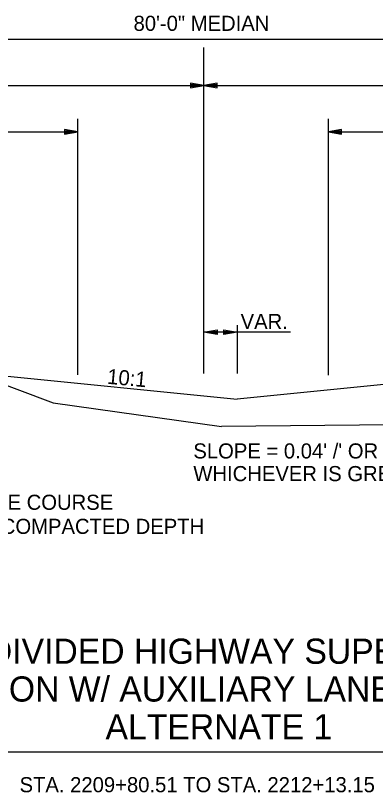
# Model space of a CAD drawing. Extents: x 1734743 to 1735935, y 759845 to 763831.
# Drawn here: x 1735746 to 1735774.6, y 762828.8 to 762890.5 of the extents above; entities that cross this region are included whole.
import ezdxf

# ---------------------------------------------------------------- set-up
doc = ezdxf.new("R2010")
doc.units = 0
for name, color, linetype in [('1', 7, 'Continuous'), ('10', 7, 'Continuous'), ('11', 7, 'Continuous'), ('19', 7, 'Continuous'), ('7', 7, 'Continuous'), ('9', 7, 'Continuous')]:
    doc.layers.add(name, color=color, linetype=linetype)

msp = doc.modelspace()

# ---------------------------------------------------------------- linework, layer by layer
at = {"layer": '1'}
msp.add_line((1735726.589, 762832.047), (1735798.51, 762832.047), dxfattribs=at)
at = {"layer": '11'}
msp.add_line((1735792.763, 762858.202), (1735762.354, 762857.892), dxfattribs=at)
at = {"layer": '19'}
for p, q in [((1735720.967, 762888.656), (1735800.967, 762888.656)), ((1735759.917, 762885.153), (1735759.917, 762884.786)), ((1735760.967, 762884.97), (1735759.917, 762885.153)), ((1735760.687, 762884.996), (1735759.917, 762885.057)), ((1735762.017, 762885.153), (1735760.967, 762884.97)), ((1735762.017, 762885.057), (1735761.247, 762884.996)), ((1735762.017, 762884.786), (1735762.017, 762885.153)), ((1735720.967, 762884.97), (1735760.967, 762884.97)), ((1735759.917, 762884.786), (1735760.967, 762884.97)), ((1735759.917, 762884.873), (1735760.687, 762884.943)), ((1735760.967, 762884.97), (1735762.017, 762884.786)), ((1735760.967, 762884.97), (1735800.967, 762884.97)), ((1735761.247, 762884.943), (1735762.017, 762884.873)), ((1735750.967, 762864.527), (1735750.967, 762882.329)), ((1735770.842, 762864.527), (1735770.842, 762882.329)), ((1735749.917, 762881.467), (1735749.917, 762881.099)), ((1735750.967, 762881.283), (1735749.917, 762881.467)), ((1735750.687, 762881.309), (1735749.917, 762881.37)), ((1735771.892, 762881.467), (1735770.842, 762881.283)), ((1735771.892, 762881.37), (1735771.122, 762881.309)), ((1735771.892, 762881.099), (1735771.892, 762881.467)), ((1735720.967, 762881.283), (1735750.967, 762881.283)), ((1735749.917, 762881.099), (1735750.967, 762881.283)), ((1735749.917, 762881.187), (1735750.687, 762881.257)), ((1735770.842, 762881.283), (1735771.892, 762881.099)), ((1735770.842, 762881.283), (1735800.967, 762881.283)), ((1735771.122, 762881.257), (1735771.892, 762881.187)), ((1735760.969, 762865.372), (1735762.019, 762865.556)), ((1735762.019, 762865.188), (1735760.969, 762865.372)), ((1735761.249, 762865.398), (1735762.019, 762865.459)), ((1735762.019, 762865.276), (1735761.249, 762865.346)), ((1735762.019, 762865.556), (1735762.019, 762865.188)), ((1735762.555, 762865.188), (1735762.555, 762865.556)), ((1735762.555, 762865.556), (1735763.605, 762865.372)), ((1735762.555, 762865.468), (1735763.325, 762865.398)), ((1735763.605, 762865.372), (1735762.555, 762865.188)), ((1735763.325, 762865.346), (1735762.555, 762865.284)), ((1735750.967, 762862.001), (1735750.967, 762864.527)), ((1735770.842, 762861.972), (1735770.842, 762864.527)), ((1735741.096, 762862.307), (1735763.605, 762860.056)), ((1735782.461, 762861.942), (1735763.605, 762860.056))]:
    msp.add_line(p, q, dxfattribs=at)
msp.add_lwpolyline([(1735716.449, 762866.88), (1735723.531, 762867.254), (1735735.42, 762864.874), (1735749.006, 762859.774), (1735762.354, 762857.892)], dxfattribs=at)
at = {"layer": '7'}
msp.add_line((1735760.969, 762862.101), (1735760.969, 762887.988), dxfattribs=at)
at = {"layer": '9'}
for p, q in [((1735763.605, 762865.926), (1735763.605, 762862.101)), ((1735767.85, 762865.372), (1735760.969, 762865.372))]:
    msp.add_line(p, q, dxfattribs=at)

# ---------------------------------------------------------------- texts
at = {"layer": '10'}
for s, height, p in [('VAR.', 1.2, (1735763.883, 762865.631)), ("SLOPE = 0.04' /' OR S.E. SLOPE", 1.2, (1735760.133, 762855.349)), ('WHICHEVER IS GREATER', 1.2, (1735760.133, 762853.549)), ('I-57 TYPICAL DIVIDED HIGHWAY SUPERELEVATED', 2, (1735726.589, 762839.047)), ('SECTION W/ AUXILIARY LANE LT.', 2, (1735737.62, 762836.047)), ('ALTERNATE 1', 2, (1735753.164, 762833.047))]:
    msp.add_text(s, height=height, dxfattribs=at).set_placement(p)
at = {"layer": '19'}
for s, p in [('80\'-0" MEDIAN', (1735755.389, 762889.303)), ('STA. 2209+80.51 TO STA. 2212+13.15', (1735746.345, 762828.847))]:
    msp.add_text(s, height=1.2, dxfattribs=at).set_placement(p)
for s, rotation, p in [('10:1', 354.84221, (1735753.258, 762861.284)), ('AGGREGATE BASE COURSE', 360, (1735731.571, 762851.273)), ('(CLASS 7) - VAR. COMPACTED DEPTH', 360, (1735731.571, 762849.361))]:
    msp.add_text(s, height=1.2, rotation=rotation, dxfattribs=at).set_placement(p)

doc.saveas('drawing.dxf')
